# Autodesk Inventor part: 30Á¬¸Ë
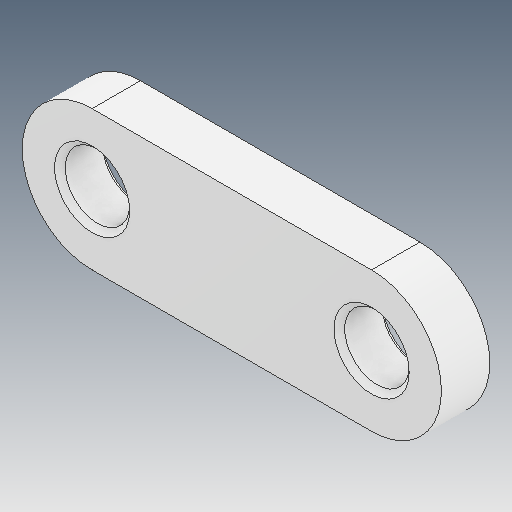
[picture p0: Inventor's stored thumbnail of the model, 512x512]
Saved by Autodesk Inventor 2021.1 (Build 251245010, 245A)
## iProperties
Created: 2021-05
Part Number: 30Á¬¸Ë
Material: Ogólny
Document SubType Name: Modeling
Designer: user
Density: 1 g/cm^3
Appearance: Domyślna
Author: user
Revision Number: ÈÎºÎ
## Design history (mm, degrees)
feature "ÊäÈë1"
node "Bryła1"
